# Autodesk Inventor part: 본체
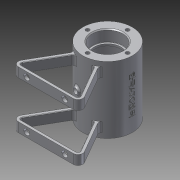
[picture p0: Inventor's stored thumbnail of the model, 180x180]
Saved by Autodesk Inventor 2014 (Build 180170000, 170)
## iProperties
Created: 2016-03
Part Number: 본체
Material: Aluminum 6061
Document SubType Name: Modeling
Designer: user
Density: 2.71 g/cm^3
Appearance: Aluminum - Flat
Mass: 209.602 g
Surface Area: 327.231 cm^2
Volume: 77.3441 cm^3
Author: user
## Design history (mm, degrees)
sketch "Sketch1"
  geometry: C1 r 26 at (0, 0); 1 further point
  constraints: 1 centre point, 1 coincident
  dimensions: "d0" = 52 diameter of C1
extrude "Extrusion1" new body sketch "Sketch1" distance "d1" = 35; taper "d2" = 0 deg
sketch "Sketch2"
  geometry: 4 further points
hole "Hole1" sketch "Sketch2" at (0, 21), (-21, 0), (0, -21), (21, 0) diameter "d5" = 4; stored, may be unused: countersink angle "d9" = 82 deg, drill point angle "d11" = 118 deg; dims "d6" = 5.984, "d7" = 3.023, "d8" = 2, "d10" = 8
sketch "Sketch3"
  geometry: C1 r 26 at (0, 0) reference; C2 r 16 at (0, 0)
  constraints: 1 centre point, 1 coincident
  dimensions: "d12" = 32 diameter of C2
extrude "Extrusion2" cut sketch "Sketch3" distance "d13" = 12; taper "d14" = 0 deg
sketch "Sketch4"
  geometry: C1 r 16 at (0, 0) reference; C2 r 14 at (0, 0)
  constraints: 1 centre point, 1 coincident
  dimensions: "d15" = 28 diameter of C2
extrude "Extrusion3" cut sketch "Sketch4" distance "d16" = 2; taper "d17" = 0 deg
sketch "Sketch5"
  geometry: C1 r 26 at (0, 0) reference; C2 r 21 at (0, 0)
  constraints: 1 centre point, 1 coincident
  dimensions: "d18" = 42 diameter of C2
extrude "Extrusion4" cut sketch "Sketch5" distance "d19" = 21; taper "d20" = 0 deg
fillet "Fillet1" dims "d21" = 0.3
workplane "Work Plane1"
sketch "Sketch6"
  geometry: L1 (13, -22.517)-(33.198, -57.5); L2 (28.868, -65)-(-28.868, -65); L3 (-33.198, -57.5)-(-13, -22.517); L4 (-28.868, -62)-(28.868, -62); L5 (30.6, -59)-(10.315, -23.866); L6 (-10.315, -23.866)-(-30.6, -59); A1 r 5 centre (28.868, -60) between (28.868, -65) and (33.198, -57.5); A2 r 5 centre (-28.868, -60) between (-33.198, -57.5) and (-28.868, -65); A3 r 2 centre (28.868, -60) between (28.868, -62) and (30.6, -59); A4 r 2 centre (-28.868, -60) between (-30.6, -59) and (-28.868, -62); A5 r 26 centre (0, 0) between (-13, -22.517) and (-10.315, -23.866); A6 r 26 centre (0, 0) between (10.315, -23.866) and (13, -22.517); 1 further point
  constraints: 12 end point, 12 point on circle, 6 centre point, 4 tangent, 1 coincident, 1 equal radius, 1 horizontal, 1 other
  dimensions: "d23" = 65 distance from line of L2 point (0, 0); "d24" = 60 deg angle of L2 L1; "d25" = 60 deg angle of L2 L3; "d26" = 5 radius of A1; "d27" = 3 distance between parallel lines of L2 L4
extrude "Extrusion5" join sketch "Sketch6" distance "d29" = 10; taper "d30" = 0 deg
sketch "Sketch7"
  geometry: L1 (57.735, 0)-(57.735, -10) reference; L2 (-20.076, -5)-(63.87, -5); L3 (28.868, 5.708)-(28.868, -22.708); C1 r 3 at (8.868, -5); C2 r 3 at (48.868, -5); 1 further point
  constraints: 4 end point, 2 centre point, 2 perpendicular, 1 point on line, 1 symmetric about line, 1 other
  dimensions: "d31" = 6 diameter of C1; "d32" = 40 diameter of C1.centre L3
extrude "Extrusion6" cut sketch "Sketch7" distance "d33" = 10; taper "d34" = 0 deg
fillet "Fillet2" dims "d35" = 3
fillet "Fillet3" dims "d36" = 0.5
fillet "Fillet4" dims "d37" = 3
chamfer "Chamfer1" distance "d38" = 1; stored, may be unused: second distance "d39" = 2, angle "d40" = 45 deg
mirror "Mirror1"
workplane "Work Plane2"
sketch "Sketch8"
  geometry: C1 r 5 at (0, 0); 1 further point
  constraints: 1 centre point, 1 coincident
  dimensions: "d42" = 10 diameter of C1
extrude "Extrusion7" join sketch "Sketch8" stored distance "d43" = 3; taper "d44" = 0 deg
fillet "Fillet5" dims "d45" = 2
sketch "Sketch9"
  geometry: A1 r 5 centre (0, 0) between (-3.763, 3.293) and (-3.763, -3.293) reference; A2 r 5 centre (0, 0) between (3.763, -3.293) and (3.763, 3.293) reference; 1 further point
  constraints: 1 coincident
hole "Hole2" sketch "Sketch9" at (0, 0) diameter "d46" = 6; stored, may be unused: countersink angle "d50" = 90 deg, drill point angle "d52" = 0 deg; dims "d47" = 5.984, "d48" = 12.6, "d49" = 2, "d51" = 10
workplane "Work Plane3"
workplane "Work Plane4"
sketch "Sketch10"
  geometry: L1 (37.027, 18.388)-(37.027, -18.909); L2 (37.027, -18.909)-(-37.914, -18.909); L3 (-37.914, -18.909)-(-37.914, 18.388); L4 (-37.914, 18.388)-(37.027, 18.388); 2 further points
  constraints: 1 coincident, 2 other
emboss "Emboss1" sketch "Sketch10" dims "d1" = 35, "d55" = 0.5, "d56" = 0
sketch "Sketch11"
  geometry: L1 (0, 0)-(-12.906, -48.164); L2 (0, 0)-(0, -50.645); L3 (-54.047, -12.43)-(49.71, -40.232)
  constraints: 6 end point, 1 perpendicular, 1 vertical
  dimensions: "d57" = 15 deg angle of L2 L1
workplane "Work Plane5"
sketch "Sketch12"
  geometry: C1 r 3 at (48.988, 0); 1 further point
  constraints: 1 centre point, 1 coincident
  dimensions: "d59" = 6 diameter of C1
extrude "Extrusion8" join sketch "Sketch12" stored distance "d60" = 6; taper "d61" = 0 deg
fillet "Fillet6" dims "d62" = 2
sketch "Sketch13"
  geometry: C1 r 3 at (0, 0) reference; 1 further point
  constraints: 1 coincident
hole "Hole3" sketch "Sketch13" at (0, 0) diameter "d63" = 6; stored, may be unused: countersink angle "d67" = 90 deg, drill point angle "d69" = 0 deg; dims "d64" = 5.984, "d65" = 12.6, "d66" = 2, "d68" = 20
body "Solid1"
other parameters: "d28" = 52, "d41" = 26, "d53" = -26, "d54" = 26, "d58" = 90 deg
